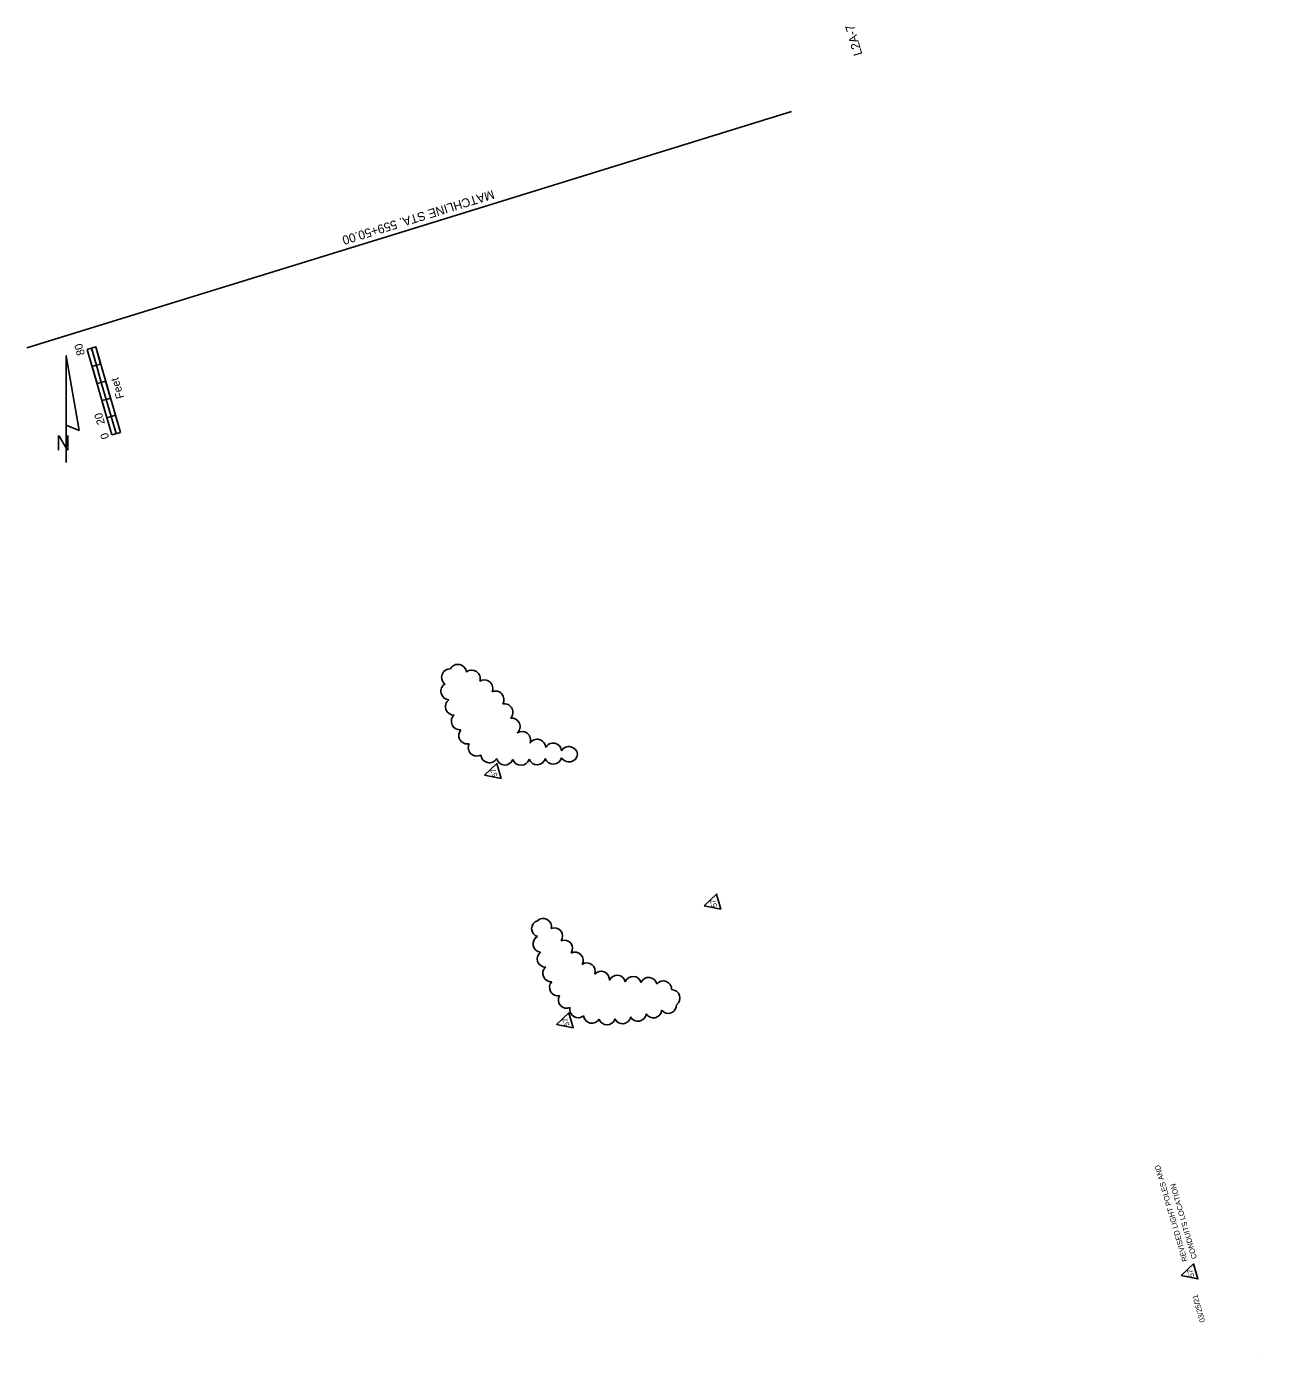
# Model space of a CAD drawing. Extents: x 929567 to 930679, y 630917 to 632116.
import ezdxf

# ---------------------------------------------------------------- set-up
doc = ezdxf.new("R2010")
doc.units = 0
for name, color, linetype in [('AdhocPoint_dp', 7, 'Continuous'), ('Cloud_dp', 7, 'Continuous'), ('MatchLines_dp', 7, 'Continuous'), ('NorthArw_dp', 7, 'Continuous'), ('Scale_dp', 7, 'Continuous'), ('TextShtNo', 7, 'Continuous')]:
    doc.layers.add(name, color=color, linetype=linetype)

msp = doc.modelspace()

# ---------------------------------------------------------------- linework, layer by layer
at = {"layer": 'AdhocPoint_dp'}
msp.add_line((930679, 630916.7), (930679, 630916.7), dxfattribs=at)
at = {"layer": 'Cloud_dp'}
for points in [[(929978.3, 631442.4), (929993.3, 631439.4), (929989.4, 631452.9)], [(930175.9, 631324.9), (930190.9, 631321.9), (930187, 631335.4)], [(930043.2, 631218), (930058.2, 631215), (930054.3, 631228.5)], [(930605.2, 630992), (930620.1, 630989), (930616.2, 631002.5)]]:
    msp.add_lwpolyline(points, close=True, dxfattribs=at)
for centre, radius, start, end in [((929954.5, 631534.4), 7.66, 5.5058, 150.5058), ((929947.5, 631530.5), 7.65, 87.912, 232.912), ((929966.9, 631529.2), 7.66, 343.6121, 128.6121), ((929978.2, 631520.5), 7.66, 336.6003, 121.6003), ((929946.8, 631517.9), 7.66, 120.6408, 265.6408), ((929988.3, 631510.4), 7.66, 328.5763, 113.5763), ((929950.9, 631504.1), 7.66, 127.4778, 272.4778), ((929996.4, 631498.9), 7.66, 316.3742, 101.3742), ((929956.3, 631490.8), 7.66, 131.5841, 276.5841), ((930002.8, 631486), 7.66, 311.8536, 96.8536), ((929962.9, 631478.1), 7.66, 138.1702, 283.1702), ((930012.2, 631474), 7.66, 339.3284, 124.3284), ((929971.5, 631467.2), 7.66, 153.5536, 298.5536), ((930025.8, 631467), 7.66, 0.9709, 145.9709), ((930040.1, 631463.5), 7.66, 6.3374, 151.3374), ((930054.4, 631460.5), 7.66, 5.1537, 150.1537), ((929982.8, 631461.1), 7.66, 184.5003, 329.5003), ((929996.8, 631459.1), 7.66, 194.696, 339.696), ((930011.2, 631458.9), 7.66, 198.1733, 343.1733), ((930025.8, 631459.3), 7.66, 200.1006, 345.1006), ((930040.3, 631460), 7.66, 200.6329, 345.6329), ((930054.4, 631461.9), 7.65, 209.8201, 354.8201), ((930031.2, 631305.9), 7.48, 348.8904, 133.8904), ((930028.3, 631304.2), 7.48, 107.4864, 252.4864), ((930041.2, 631297.5), 7.48, 326.0368, 111.0368), ((930029.6, 631290.5), 7.48, 118.7932, 263.7932), ((930050.2, 631286.4), 7.48, 326.7972, 111.7972), ((930033.3, 631277.1), 7.48, 126.6481, 271.6481), ((930059.8, 631275.6), 7.48, 331.4745, 116.4745), ((930038.3, 631263.9), 7.48, 129.9252, 274.9252), ((930070.6, 631265.9), 7.48, 339.5799, 124.5799), ((930083.3, 631258.4), 7.48, 354.7669, 139.7669), ((930044.4, 631251.3), 7.48, 136.5558, 281.5558), ((930097.7, 631254.9), 7.48, 12.2119, 157.2119), ((930112, 631253.8), 7.48, 14.6563, 159.6563), ((930126.1, 631252.9), 7.48, 12.317, 157.317), ((930139.3, 631249.8), 7.48, 356.6661, 141.6661), ((930052.3, 631240.1), 7.48, 148.9783, 293.9783), ((930146.8, 631241.9), 7.47, 305.3877, 90.3877), ((930062.6, 631231.5), 7.48, 166.3616, 311.3616), ((930130.3, 631231.4), 7.48, 211.177, 356.177), ((930143.7, 631235.5), 7.48, 217.5956, 2.5956), ((930075, 631226.6), 7.48, 185.6024, 330.6024), ((930088.6, 631225.2), 7.48, 197.6455, 342.6455), ((930102.5, 631226.1), 7.48, 204.6776, 349.6776), ((930116.4, 631228.4), 7.48, 208.7217, 353.7217)]:
    msp.add_arc(centre, radius, start, end, dxfattribs=at)
at = {"layer": 'MatchLines_dp'}
msp.add_lwpolyline([(930254.5, 632039.5), (929910.6, 631933.2), (929566.6, 631827)], dxfattribs=at)
at = {"layer": 'NorthArw_dp'}
msp.add_line((929602.2, 631723.7), (929602.2, 631819.7), dxfattribs=at)
msp.add_lwpolyline([(929602.2, 631757.3), (929602.2, 631819.7), (929613.7, 631752.5)], close=True, dxfattribs=at)
at = {"layer": 'Scale_dp'}
for p, q in [((929628.7, 631827.7), (929621, 631825.5)), ((929621, 631825.5), (929643.2, 631748.6)), ((929650.9, 631750.8), (929628.7, 631827.7)), ((929643.2, 631748.6), (929650.9, 631750.8))]:
    msp.add_line(p, q, dxfattribs=at)
for points in [[(929633.1, 631812.3), (929629.3, 631811.2), (929624.8, 631826.6), (929628.7, 631827.7)], [(929633.7, 631795.8), (929629.9, 631794.7), (929625.4, 631810.1), (929629.3, 631811.2)], [(929642, 631781.6), (929638.1, 631780.5), (929633.7, 631795.8), (929637.5, 631796.9)], [(929642.6, 631765.1), (929638.7, 631764), (929634.3, 631779.4), (929638.1, 631780.5)], [(929650.9, 631750.8), (929647, 631749.7), (929642.6, 631765.1), (929646.4, 631766.2)]]:
    msp.add_lwpolyline(points, close=True, dxfattribs=at)

# ---------------------------------------------------------------- texts
at = {"layer": 'Cloud_dp'}
for s, p in [('57', (929990.2, 631441.6)), ('57', (930187.8, 631324.1)), ('57', (930055, 631217.2)), ('REVISED LIGHT POLES AND', (930610.9, 631005.4)), ('CONDUITS LOCATION', (930619.3, 631007.8)), ('57', (930617, 630991.2)), ('03/25/21', (930626.7, 630950.7))]:
    msp.add_text(s, height=4.8, rotation=106.1194, dxfattribs=at).set_placement(p)
at = {"layer": 'MatchLines_dp'}
msp.add_text('MATCHLINE STA. 559+50.00', height=8, rotation=197.1694, dxfattribs=at).set_placement((929985.8, 631969.1))
at = {"layer": 'NorthArw_dp'}
msp.add_text('N', height=13.4, dxfattribs=at).set_placement((929593, 631734.6))
at = {"layer": 'Scale_dp'}
for s, p in [('80', (929619.1, 631821.1)), ('Feet', (929654.3, 631782.2)), ('20', (929637.1, 631758.8)), ('0', (929640.9, 631745.9))]:
    msp.add_text(s, height=7.2, rotation=106.1194, dxfattribs=at).set_placement(p)
at = {"layer": 'TextShtNo'}
msp.add_text('L2A-7 ', height=8, rotation=106.1194, dxfattribs=at).set_placement((930318.4, 632091))

doc.saveas('drawing.dxf')
